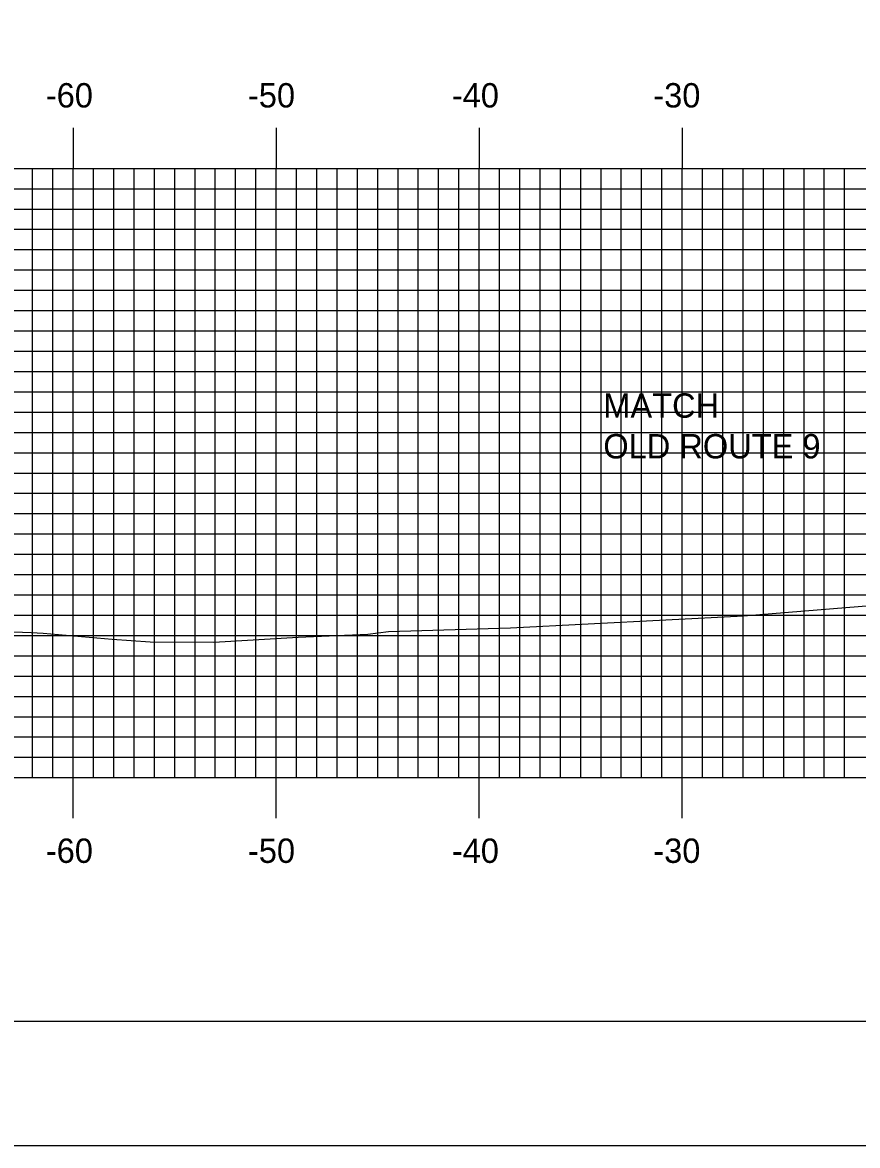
# Model space of a CAD drawing. Extents: x 852922 to 853266, y 364785 to 365005.
# Drawn here: x 853025.7 to 853066.9, y 364785.1 to 364840.4 of the extents above; entities that cross this region are included whole.
import ezdxf

# ---------------------------------------------------------------- set-up
doc = ezdxf.new("R2010")
doc.units = 0
for name, color, linetype in [('ANNOTATION', 7, 'Continuous'), ('BORDER', 7, 'Continuous'), ('H_V ANNOTATION', 7, 'Continuous'), ('MAJOR', 7, 'Continuous'), ('MINOR', 7, 'Continuous'), ('PLOT BOUNDARY', 7, 'Continuous'), ('S_Roadway_Centerline', 7, 'Continuous')]:
    doc.layers.add(name, color=color, linetype=linetype)

msp = doc.modelspace()

# ---------------------------------------------------------------- linework, layer by layer
at = {"layer": 'BORDER'}
msp.add_lwpolyline([(852938.644, 364791.233), (853258.644, 364791.233), (853258.644, 365001.233), (852938.644, 365001.233)], close=True, dxfattribs=at)
at = {"layer": 'MAJOR'}
for p, q in [((853028.244, 364835.237), (853028.244, 364833.233)), ((853038.244, 364835.237), (853038.244, 364833.233)), ((853048.244, 364835.237), (853048.244, 364833.233)), ((853058.244, 364835.237), (853058.244, 364833.233)), ((852948.244, 364833.233), (853228.244, 364833.233)), ((852948.244, 364833.233), (853228.244, 364833.233)), ((853028.244, 364803.233), (853028.244, 364833.233)), ((853038.244, 364803.233), (853038.244, 364833.233)), ((853048.244, 364803.233), (853048.244, 364833.233)), ((853058.244, 364803.233), (853058.244, 364833.233)), ((852948.244, 364828.233), (853228.244, 364828.233)), ((852948.244, 364823.233), (853228.244, 364823.233)), ((852948.244, 364818.233), (853228.244, 364818.233)), ((852948.244, 364813.233), (853228.244, 364813.233)), ((852948.244, 364808.233), (853228.244, 364808.233)), ((852948.244, 364803.233), (853228.244, 364803.233)), ((852948.244, 364803.233), (853228.244, 364803.233)), ((853028.244, 364801.229), (853028.244, 364803.233)), ((853038.244, 364801.229), (853038.244, 364803.233)), ((853048.244, 364801.229), (853048.244, 364803.233)), ((853058.244, 364801.229), (853058.244, 364803.233))]:
    msp.add_line(p, q, dxfattribs=at)
at = {"layer": 'MINOR'}
for p, q in [((853026.244, 364803.233), (853026.244, 364833.233)), ((853027.244, 364803.233), (853027.244, 364833.233)), ((853029.244, 364803.233), (853029.244, 364833.233)), ((853030.244, 364803.233), (853030.244, 364833.233)), ((853031.244, 364803.233), (853031.244, 364833.233)), ((853032.244, 364803.233), (853032.244, 364833.233)), ((853033.244, 364803.233), (853033.244, 364833.233)), ((853034.244, 364803.233), (853034.244, 364833.233)), ((853035.244, 364803.233), (853035.244, 364833.233)), ((853036.244, 364803.233), (853036.244, 364833.233)), ((853037.244, 364803.233), (853037.244, 364833.233)), ((853039.244, 364803.233), (853039.244, 364833.233)), ((853040.244, 364803.233), (853040.244, 364833.233)), ((853041.244, 364803.233), (853041.244, 364833.233)), ((853042.244, 364803.233), (853042.244, 364833.233)), ((853043.244, 364803.233), (853043.244, 364833.233)), ((853044.244, 364803.233), (853044.244, 364833.233)), ((853045.244, 364803.233), (853045.244, 364833.233)), ((853046.244, 364803.233), (853046.244, 364833.233)), ((853047.244, 364803.233), (853047.244, 364833.233)), ((853049.244, 364803.233), (853049.244, 364833.233)), ((853050.244, 364803.233), (853050.244, 364833.233)), ((853051.244, 364803.233), (853051.244, 364833.233)), ((853052.244, 364803.233), (853052.244, 364833.233)), ((853053.244, 364803.233), (853053.244, 364833.233)), ((853054.244, 364803.233), (853054.244, 364833.233)), ((853055.244, 364803.233), (853055.244, 364833.233)), ((853056.244, 364803.233), (853056.244, 364833.233)), ((853057.244, 364803.233), (853057.244, 364833.233)), ((853059.244, 364803.233), (853059.244, 364833.233)), ((853060.244, 364803.233), (853060.244, 364833.233)), ((853061.244, 364803.233), (853061.244, 364833.233)), ((853062.244, 364803.233), (853062.244, 364833.233)), ((853063.244, 364803.233), (853063.244, 364833.233)), ((853064.244, 364803.233), (853064.244, 364833.233)), ((853065.244, 364803.233), (853065.244, 364833.233)), ((853066.244, 364803.233), (853066.244, 364833.233)), ((852948.244, 364832.233), (853228.244, 364832.233)), ((852948.244, 364831.233), (853228.244, 364831.233)), ((852948.244, 364830.233), (853228.244, 364830.233)), ((852948.244, 364829.233), (853228.244, 364829.233)), ((852948.244, 364827.233), (853228.244, 364827.233)), ((852948.244, 364826.233), (853228.244, 364826.233)), ((852948.244, 364825.233), (853228.244, 364825.233)), ((852948.244, 364824.233), (853228.244, 364824.233)), ((852948.244, 364822.233), (853228.244, 364822.233)), ((852948.244, 364821.233), (853228.244, 364821.233)), ((852948.244, 364820.233), (853228.244, 364820.233)), ((852948.244, 364819.233), (853228.244, 364819.233)), ((852948.244, 364817.233), (853228.244, 364817.233)), ((852948.244, 364816.233), (853228.244, 364816.233)), ((852948.244, 364815.233), (853228.244, 364815.233)), ((852948.244, 364814.233), (853228.244, 364814.233)), ((852948.244, 364812.233), (853228.244, 364812.233)), ((852948.244, 364811.233), (853228.244, 364811.233)), ((852948.244, 364810.233), (853228.244, 364810.233)), ((852948.244, 364809.233), (853228.244, 364809.233)), ((852948.244, 364807.233), (853228.244, 364807.233)), ((852948.244, 364806.233), (853228.244, 364806.233)), ((852948.244, 364805.233), (853228.244, 364805.233)), ((852948.244, 364804.233), (853228.244, 364804.233))]:
    msp.add_line(p, q, dxfattribs=at)
at = {"layer": 'PLOT BOUNDARY'}
msp.add_lwpolyline([(852922.457, 364785.114), (853262.457, 364785.114), (853262.457, 365005.114), (852922.457, 365005.114)], close=True, dxfattribs=at)
at = {"layer": 'S_Roadway_Centerline'}
msp.add_lwpolyline([(853020.506, 364810.596), (853026.177, 364810.385), (853026.769, 364810.349), (853030.166, 364810.057), (853032.037, 364809.917), (853035.178, 364809.91), (853039.326, 364810.149), (853042.753, 364810.304), (853043.773, 364810.422), (853049.791, 364810.616), (853061.255, 364811.205), (853082.225, 364812.904), (853093.01, 364815.011), (853100.321, 364816.342), (853115.647, 364818.92), (853120.262, 364818.469), (853132.036, 364817.907), (853136.96, 364818.156), (853147.961, 364817.695), (853159.64, 364818.86)], dxfattribs=at)

# ---------------------------------------------------------------- texts
at = {"layer": 'ANNOTATION'}
for s, p in [('MATCH', (853054.358, 364820.955)), ('OLD ROUTE 9', (853054.358, 364818.951))]:
    msp.add_text(s, height=1.2, dxfattribs=at).set_placement(p)
at = {"layer": 'H_V ANNOTATION'}
for s, p in [('-60', (853026.895, 364836.233)), ('-50', (853036.852, 364836.233)), ('-40', (853046.895, 364836.233)), ('-30', (853056.82, 364836.233)), ('-60', (853026.895, 364799.033)), ('-50', (853036.852, 364799.033)), ('-40', (853046.895, 364799.033)), ('-30', (853056.82, 364799.033))]:
    msp.add_text(s, height=1.2, dxfattribs=at).set_placement(p)

doc.saveas('drawing.dxf')
